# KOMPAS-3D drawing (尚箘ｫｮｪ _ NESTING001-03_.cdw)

Views: Вид 1, Снизу
Referenced files in \\Smallatom\скворечник\: Потолок.m3d, Потолок _ NESTING001-03.cdw
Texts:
  NESTING001-05
  Крыша
  Лит-Масса-Масштаб
  Материал-Предприятие
  Title Specification
  Body Specification ( left align )
  Body Specificaton ( centered )
  Поз.
  Кол.
  Приме-
  чание
  Таблица спецификации
  Демьянова Л.В.
  NESTING001-05-
  КЮТ СО РАН
Dimensions and other numbers on the sheet: 80; 120; 4,2; 4 отв.; 6; 1:2; 1; 0,24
